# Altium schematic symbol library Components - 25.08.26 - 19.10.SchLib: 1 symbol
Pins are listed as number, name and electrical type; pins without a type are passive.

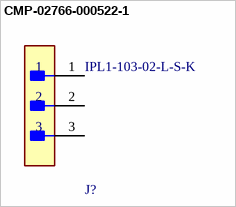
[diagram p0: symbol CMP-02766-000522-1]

## CMP-02766-000522-1
designator J?, comment IPL1-103-02-L-S-K
3 Position 1 Row .100" (2.54 mm) pitch connector; Max Voltage Rating (AC): 675V; Gender: Male; Number of Ports: 1; Pitch: 2.54mm; Max Current Rating: 7.4A; Number of Contacts: 3
footprint FP-IPL1-103-02-L-S-K-0
pins: 1, 2, 3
